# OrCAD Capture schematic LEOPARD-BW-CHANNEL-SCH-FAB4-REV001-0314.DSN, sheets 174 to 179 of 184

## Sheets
174 093_WBG - STRAPPING/MISC: size A3; title: WBG - STRAPPING/MISC
175 092_WBG - DECOUPLING 2/2: size A3; title: WBG - DECOUPLING 2/2
176 099_USB 3.0/2.0 CONNECTORS: size A3; title: USB 3/0/2/0 CONNECTORS
177 109_AST1250 CLK/VGA/USB/JTAG: size Custom; title: AST1250 CLK/VGA/USB/JTAG
178 008_POWER GOOD/RESET DIAGRAM: title: POWER GOOD/RESET DIAGRAM
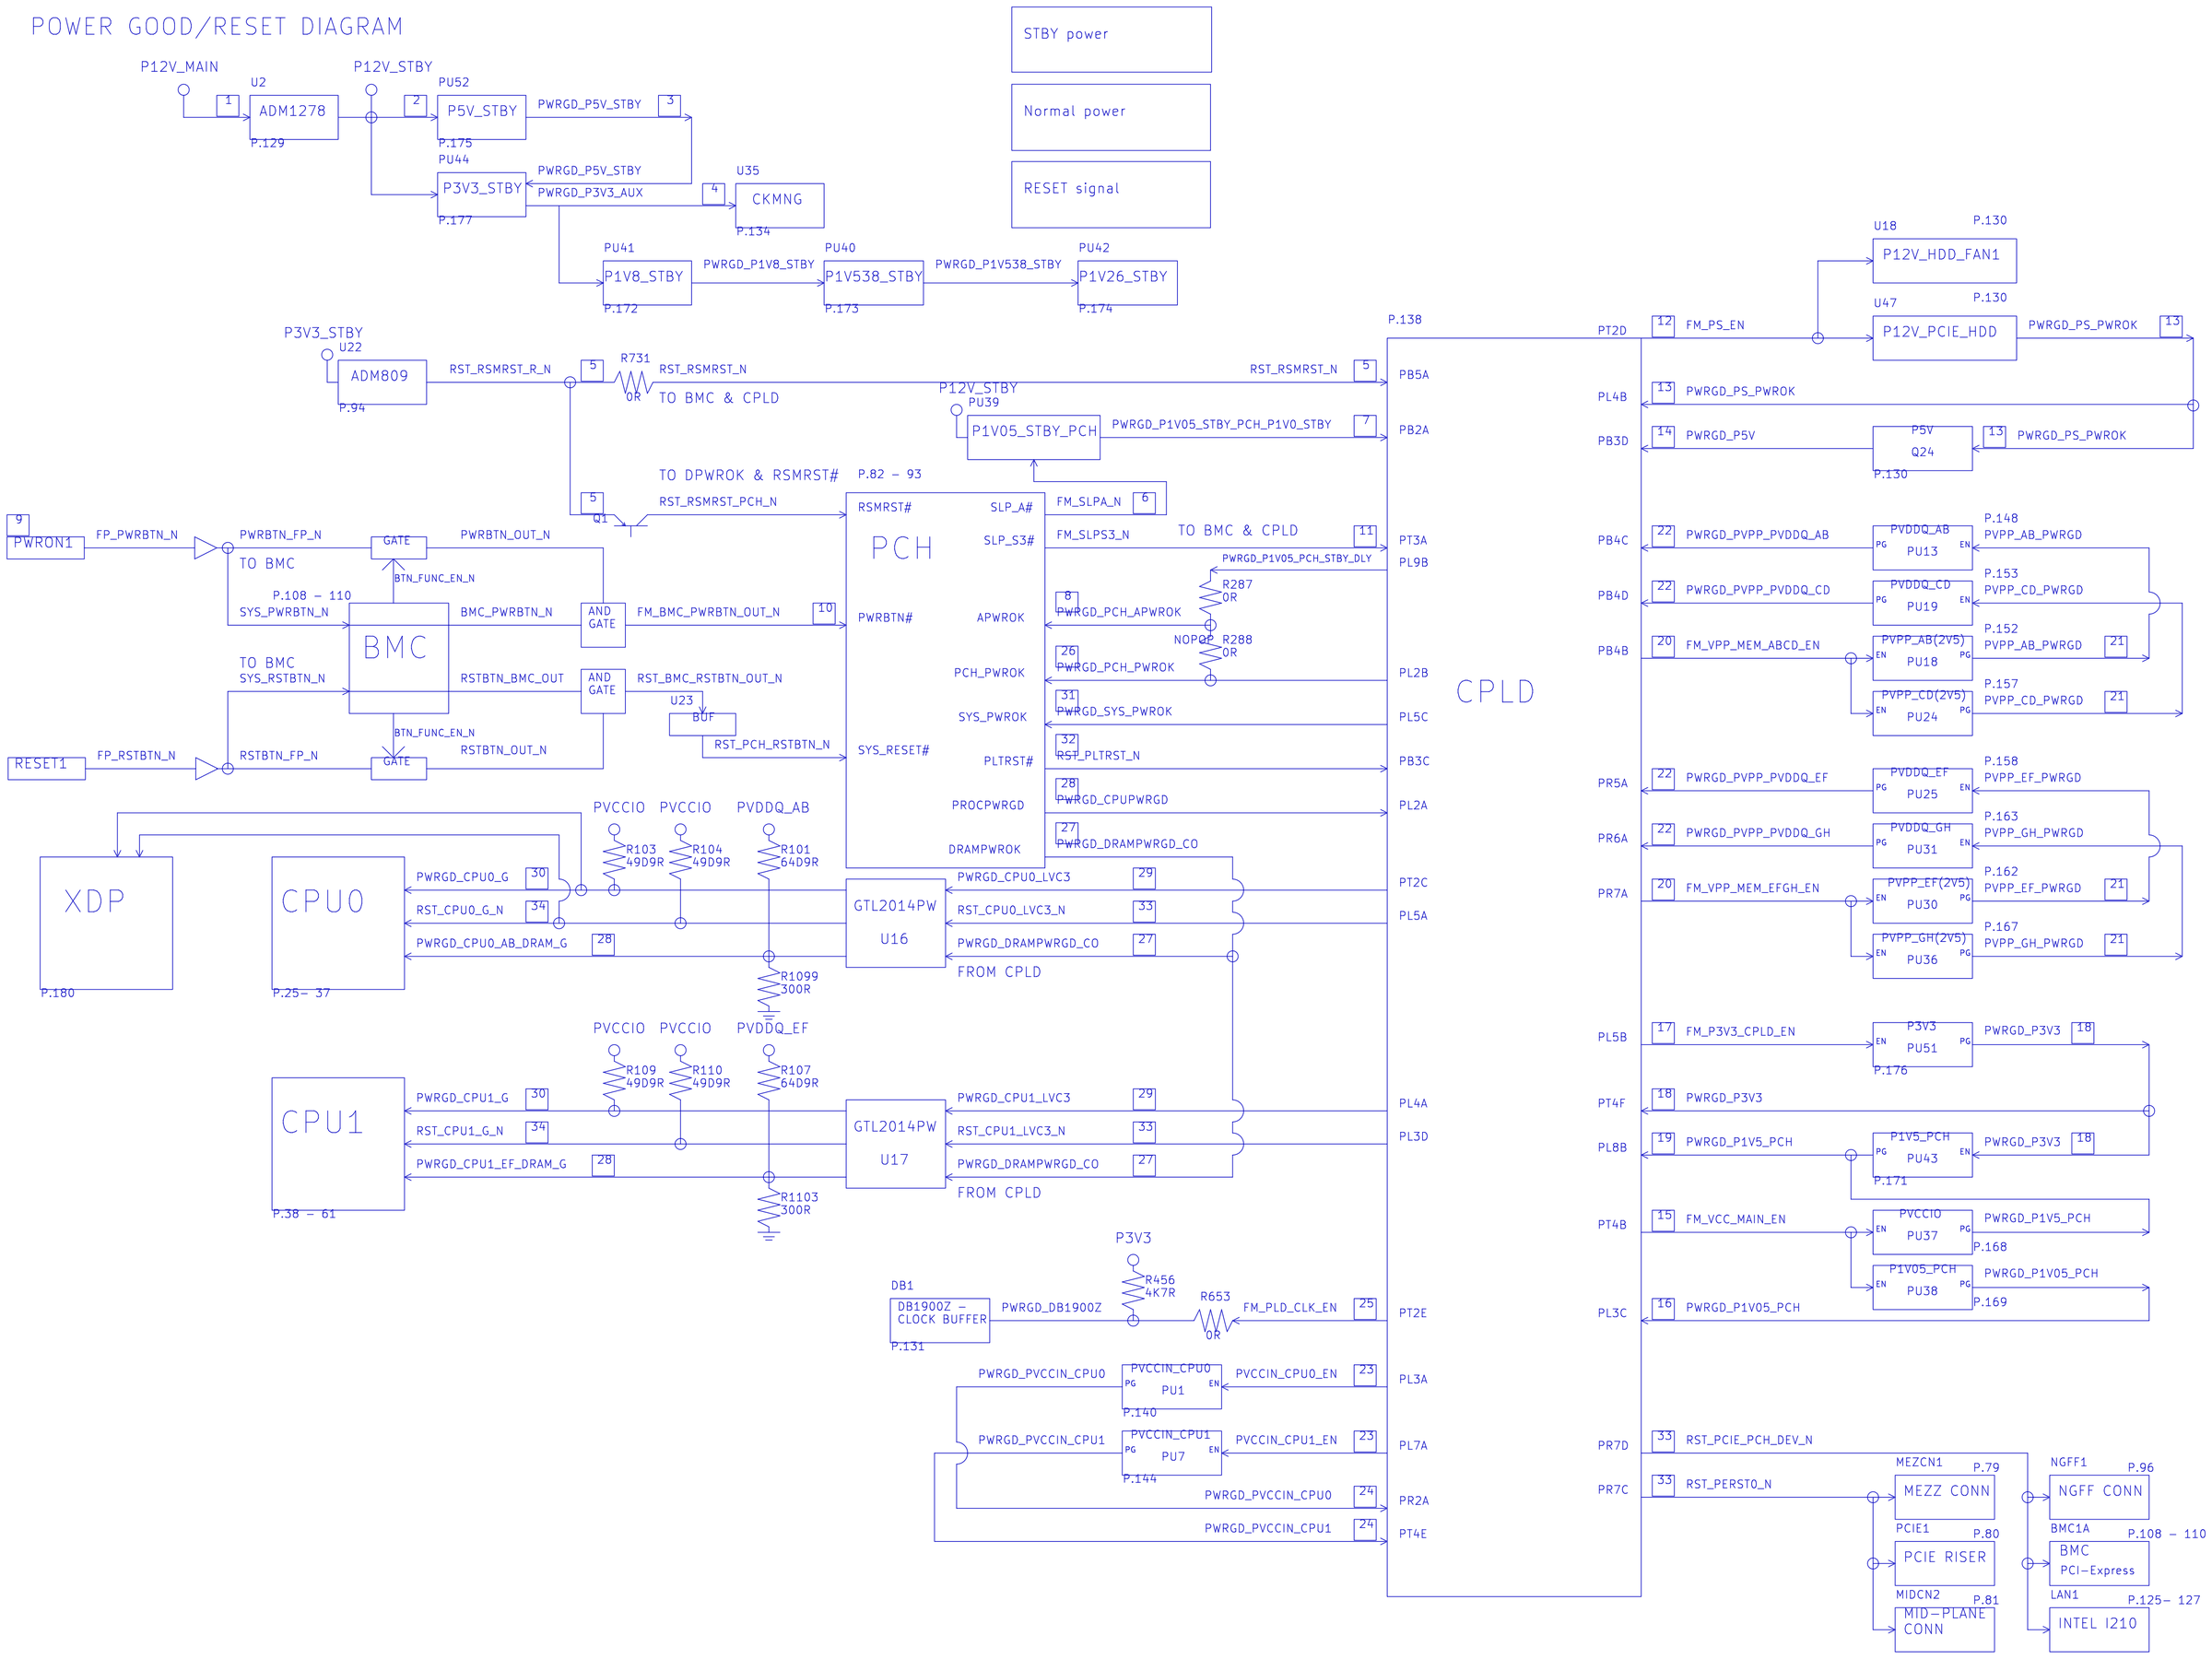
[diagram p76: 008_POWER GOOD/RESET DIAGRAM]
179 077_CPU SIDE BAND - PULL UP/DN: size A3; title: CPU SIDE BAND - PULL UP/DN
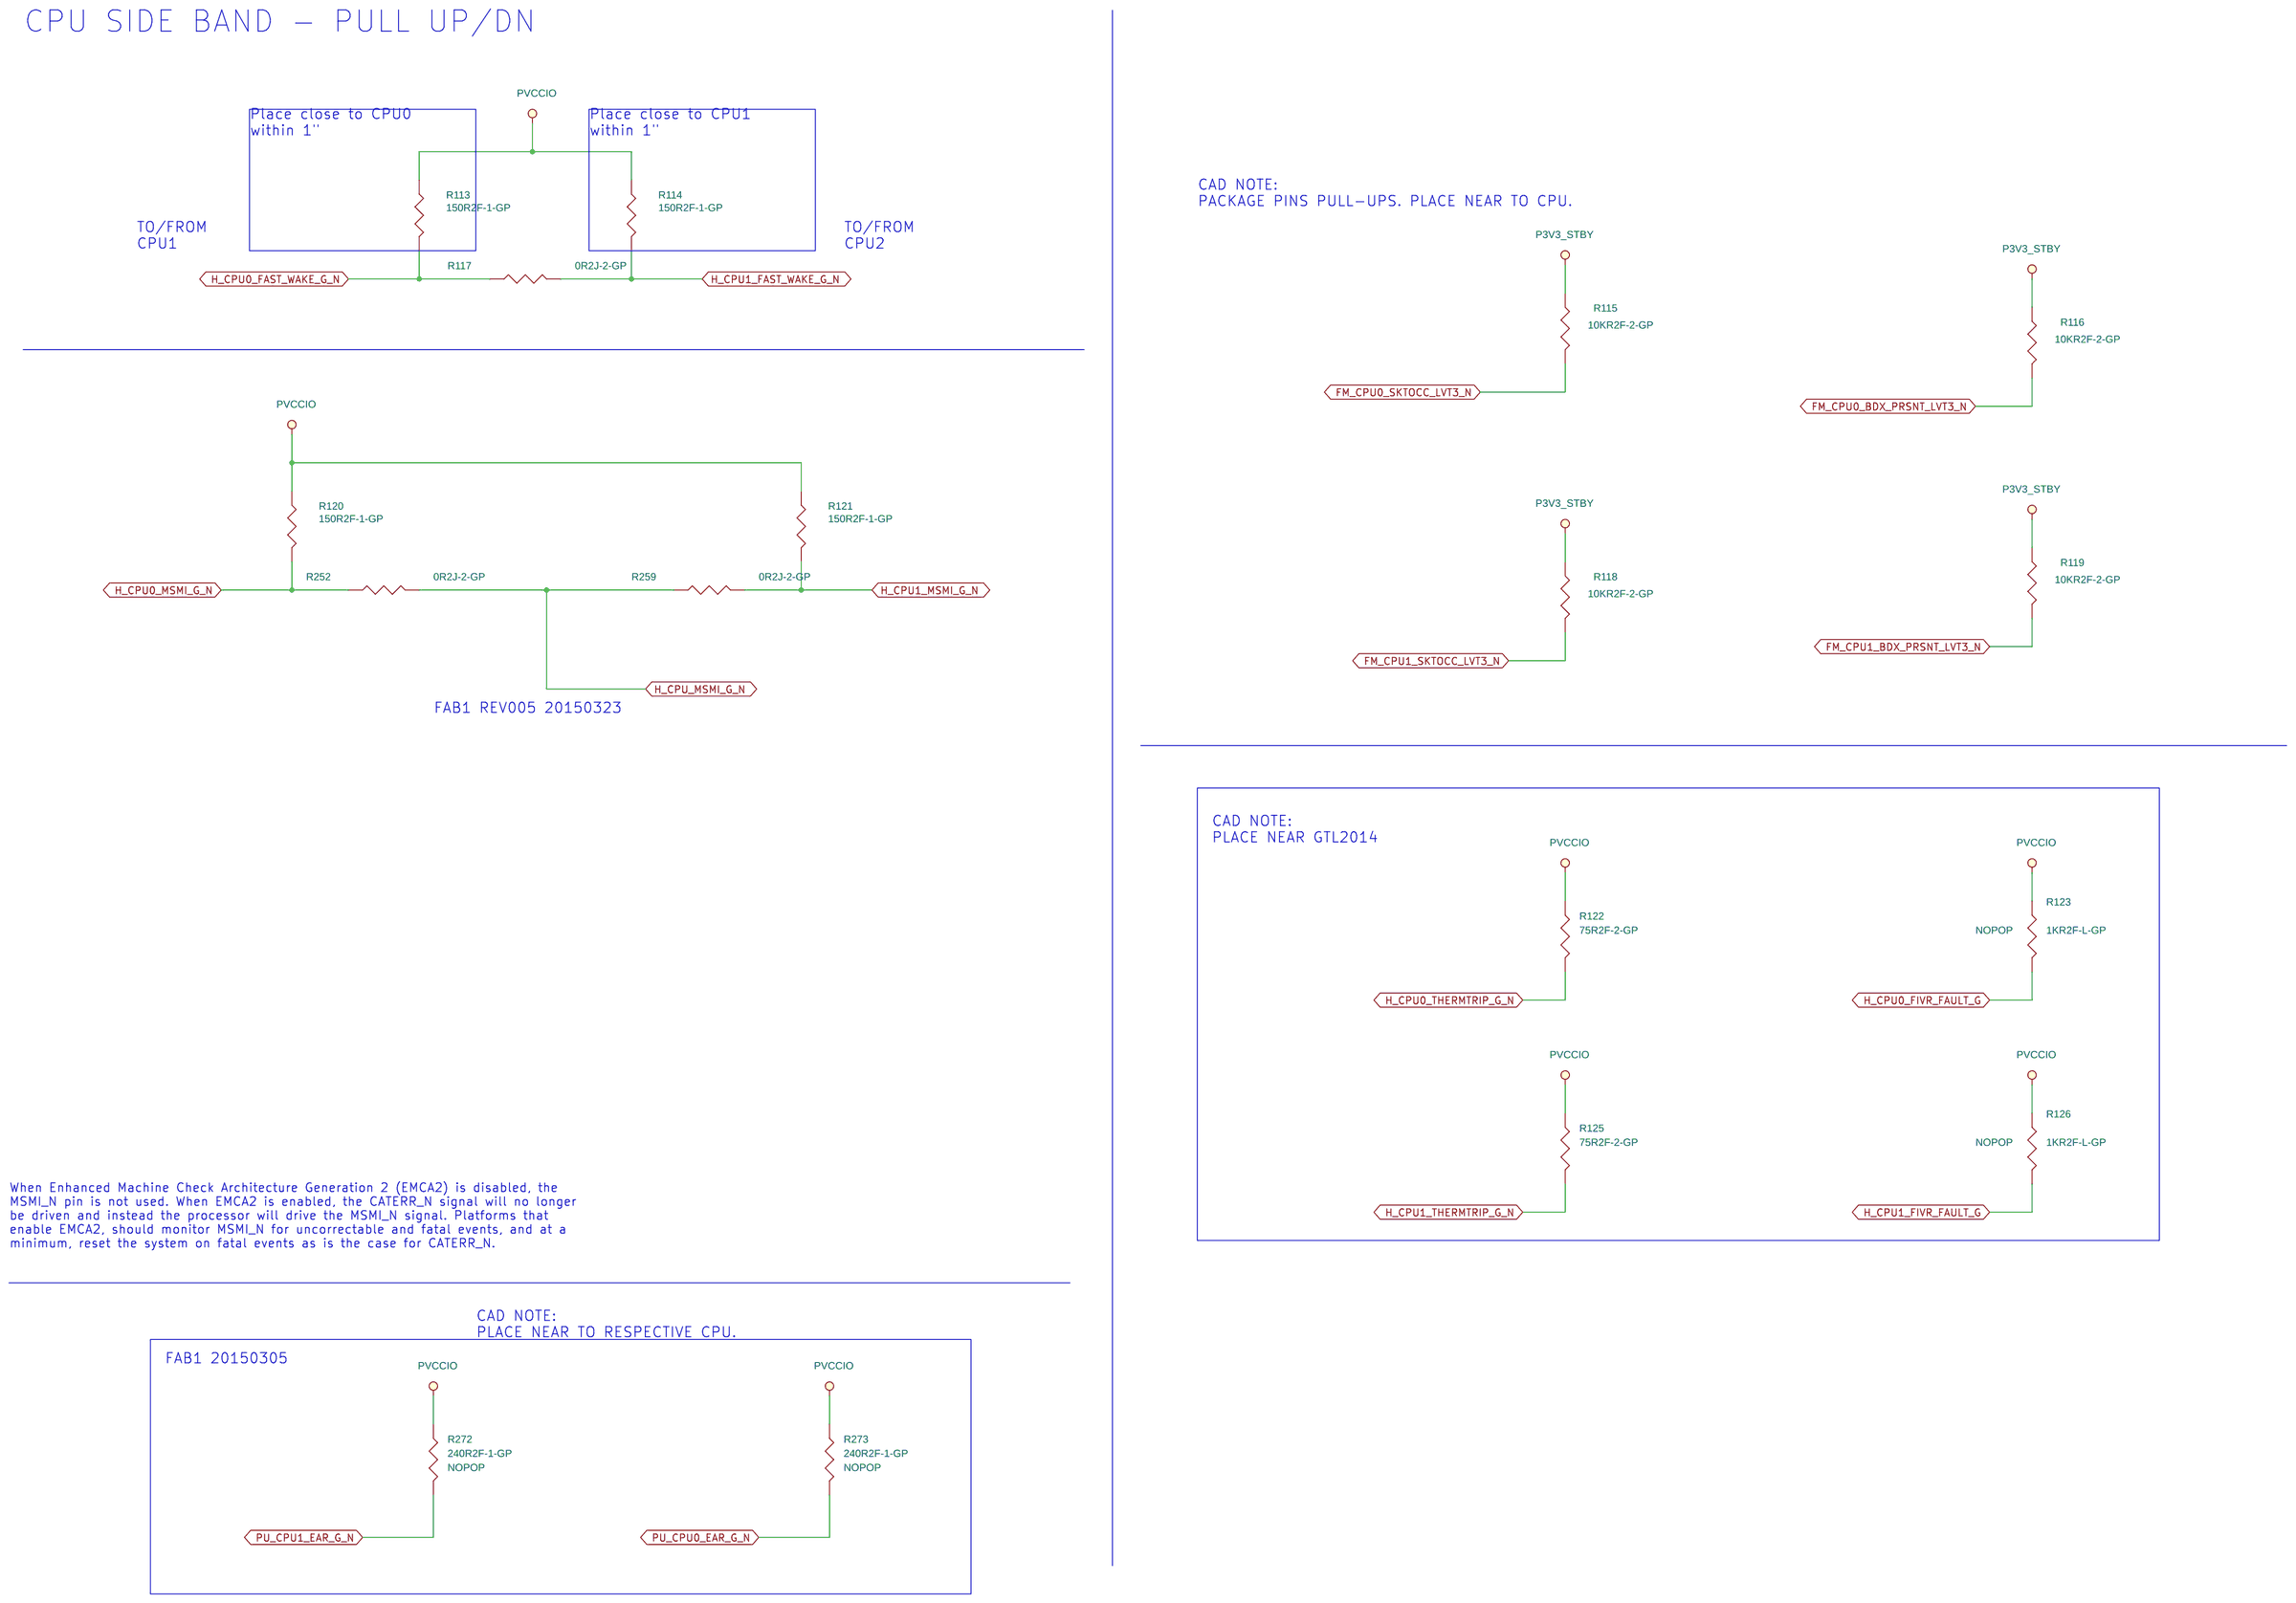
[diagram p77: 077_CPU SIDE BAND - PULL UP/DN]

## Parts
sheet 077_CPU SIDE BAND - PULL UP/DN
R113  150R2F-1-GP  [R402H16]
R114  150R2F-1-GP  [R402H16]
R115  10KR2F-2-GP  [R402H16]
R116  10KR2F-2-GP  [R402H16]
R117  0R2J-2-GP  [R402H16]
R118  10KR2F-2-GP  [R402H16]
R119  10KR2F-2-GP  [R402H16]
R120  150R2F-1-GP  [R402H16]
R121  150R2F-1-GP  [R402H16]
R122  75R2F-2-GP  [R402H16]
R123  1KR2F-L-GP  [R402H16]
R125  75R2F-2-GP  [R402H16]
R126  1KR2F-L-GP  [R402H16]
R252  0R2J-2-GP  [R402H16]
R259  0R2J-2-GP  [R402H16]
R272  240R2F-1-GP  [R402H16]
R273  240R2F-1-GP  [R402H16]
sheet 092_WBG - DECOUPLING 2/2
C257  SC1U10V2KX-4-GP  [C402H22]
C258  SC1U10V2KX-4-GP  [C402H22]
C259  SC1U10V2KX-4-GP  [C402H22]
C260  SC1U10V2KX-4-GP  [C402H22]
C261  SC1U10V2KX-4-GP  [C402H22]
C262  SC1U10V2KX-4-GP  [C402H22]
C263  SC1U10V2KX-4-GP  [C402H22]
C264  SC1U10V2KX-4-GP  [C402H22]
C265  SC10U6D3V5KX-4GP  [C805H58]
C266  SC1U10V2KX-4-GP  [C402H22]
C267  SC1U10V2KX-4-GP  [C402H22]
C268  SC1U10V2KX-4-GP  [C402H22]
C269  SC1U10V2KX-4-GP  [C402H22]
sheet 093_WBG - STRAPPING/MISC
C76  SC1U10V2KX-4-GP  [C402H22]
JP13  FCI-CON2-S-GP  [680001-202HLF]
R180  1KR2F-3-GP  [R402H16]
R191  1KR2F-3-GP  [R402H16]
R200  10KR2F-2-GP  [R402H16]
R202  10KR2F-2-GP  [R402H16]
R205  10KR2F-2-GP  [R402H16]
R207  10KR2F-2-GP  [R402H16]
R208  1KR2F-3-GP  [R402H16]
R209  1KR2F-3-GP  [R402H16]
R210  390KR2J-GP  [R402H16]
R211  1KR2F-3-GP  [R402H16]
R212  390KR2J-GP  [R402H16]
R213  10KR2F-2-GP  [R402H16]
R214  1KR2F-3-GP  [R402H16]
R215  1KR2F-3-GP  [R402H16]
R218  3K3R2F-2-GP  [R402H16]
R238  100R2F-L1-GP-U  [R402H14]
R330  0R2J-2-GP  [R402H16]
R862  100R2F-L1-GP-U  [R402H14]
R872  1KR2F-3-GP  [R402H16]
R873  1KR2F-3-GP  [R402H16]
R916  10KR2F-2-GP  [R402H16]
U82  NC7SB3157P6X-2GP  [UMT6H44]
sheet 099_USB 3.0/2.0 CONNECTORS
C332  SCD1U10V2KX-5GP  [C402H22]
C333  SCD1U10V2KX-5GP  [C402H22]
C334  SCD1U10V2KX-5GP  [C402H22]
C335  SCD1U10V2KX-5GP  [C402H22]
C7318  SCD1U16V2KX-3GP  [C402H22]
C7319  SC1KP50V2KX-1GP  [C402H22]
C7320  SC1KP50V2KX-1GP  [C402H22]
D2  PESD5V0X1BQ-1-GP  [SC75-1D6-312H24]
D5  PESD5V0X1BQ-1-GP  [SC75-1D6-312H24]
L7  FILTER-4P-204-GP  [FILTER2012-4PH48]
L28  DLW21HN900SQ2LGP-U  [L2012-4P-1MH40]
L31  DLW21HN900SQ2LGP-U  [L2012-4P-1MH40]
L35  DLW21HN900SQ2LGP-U  [L2012-4P-1MH40]
L38  DLW21HN900SQ2LGP-U  [L2012-4P-1MH40]
L47  DLW21HN900SQ2LGP-U  [L2012-4P-1MH40]
R326  0R3J-0-U-GP  [R603H22]
R331  0R3J-0-U-GP  [R603H22]
R399  10KR2F-2-GP  [R402H16]
R400  10KR2F-2-GP  [R402H16]
R577  0R3J-0-U-GP  [R603H22]
R578  0R3J-0-U-GP  [R603H22]
R594  0R3J-0-U-GP  [R603H22]
R595  0R3J-0-U-GP  [R603H22]
R598  0R3J-0-U-GP  [R603H22]
R599  0R3J-0-U-GP  [R603H22]
R784  0R3J-0-U-GP  [R603H22]
R851  0R3J-0-U-GP  [R603H22]
R6609  10KR2F-2-GP  [R402H16]
R6610  10KR2F-2-GP  [R402H16]
TC1  ST220U10VDM-9GP  [CT7343H123]
TC2  ST220U10VDM-9GP  [CT7343H123]
U30  DF10G7M1N-GP  [DFN10G2510-1H22]
U32  DF10G7M1N-GP  [DFN10G2510-1H22]
U169  AP2192MPG-13-GP  [MSOP8-1G195165H44]
USB1  SKT-USB13-27-GP  [SKT-USB13-148074]
USB2  SKT-USB13-119-GP  [SKT-USB13-071258]
sheet 107_AST1250 PCIE_LPC_DDR3_I2C
BMC1  AST1250A1-GP  [BGA408D19H52]  (sections A,B,C,D)
sheet 109_AST1250 CLK/VGA/USB/JTAG
C153  SC1U10V2KX-4-GP  [C402H22]
C154  SCD1U16V2KX-3GP  [C402H22]
C495  SC4D7U16V5KX-1-GP  [C805H56]
C512  SC100P50V2JN-3GP  [C402H22]
C7284  SC1U10V2KX-4-GP  [C402H22]
L23  BLM21PG331SN1D-2-GP  [L805H42]
OSC2  OSC-48MHZ-28-GP  [OSC-3225-4P-3H48]
Q21  2N7002-7F-GP  [SOT23DGS2D4H44]
R268  10KR2F-2-GP  [R402H16]
R333  10KR2F-2-GP  [R402H16]
R348  10KR2F-2-GP  [R402H16]
R354  10KR2F-2-GP  [R402H16]
R357  10KR2F-2-GP  [R402H16]
R358  10KR2F-2-GP  [R402H16]
R359  10KR2F-2-GP  [R402H16]
R367  10KR2F-2-GP  [R402H16]
R511  10KR2F-2-GP  [R402H16]
R515  10KR2F-2-GP  [R402H16]
R751  0R2J-2-GP  [R402H16]
R752  0R2J-2-GP  [R402H16]
R756  0R2J-2-GP  [R402H16]
R757  0R2J-2-GP  [R402H16]
R771  0R2J-2-GP  [R402H16]
R787  0R2J-2-GP  [R402H16]
R909  8K2R2J-3-GP  [R402H16]
R910  10KR2F-2-GP  [R402H16]
R911  47KR2F-GP  [R402H16]
R913  10KR2F-2-GP  [R402H16]
R914  4K7R2F-GP  [R402H16]
R915  47KR2F-GP  [R402H16]
R917  100R2F-L1-GP-U  [R402H14]
R923  10R2F-L-GP  [R402H14]
R924  0R2J-2-GP  [R402H16]
R925  100R2F-L1-GP-U  [R402H14]
R926  0R2J-2-GP  [R402H16]
R927  47KR2F-GP  [R402H16]
R929  0R2J-2-GP  [R402H16]
R930  47KR2F-GP  [R402H16]
R931  47KR2F-GP  [R402H16]
R934  47KR2F-GP  [R402H16]
R936  4K7R2F-GP  [R402H16]
R1036  10KR2F-2-GP  [R402H16]
R2033  10KR2F-2-GP  [R402H16]
R2073  0R2J-2-GP  [R402H16]
U166  SN74LVC1G07DCKR-GP  [SC70-5H44]

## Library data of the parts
R113 R114 R120 R121 = 150R2F-1-GP: CHIP RES 150 F 1/16W 0402; GREENDFACTOR: R2_SA;HF_SA;G_SA;; Package Type: SMD-RG; Part Number: 64.15005.6DL; SPEC: http://wpqssvr.wistron.com.tw:7001/wpqs/servlet/COM.qpart.Attachment?PartNumber=64.15005.6DL
R115 R116 R118 R119 = 10KR2F-2-GP: CHIP RES 10K F 1/16W 0402; GREENDFACTOR: R2_SA;HF_SA;G_SA;; Part Number: 64.10025.6DL; Part Type: SMD-RG; SPEC: http://wpqssvr.wistron.com.tw:7001/wpqs/servlet/COM.qpart.Attachment?PartNumber=64.10025.6DL
R117 R252 R259 R330 = 0R2J-2-GP: CHIP RES 0 J 1/16W 0402; Category: PCH; DESCRIPTIO: CHIP RES 0 J 1/16W 0402; GREENDFACTOR: R2_SA;HF_SA;G_SA;; Package Type: SMD-RG; Part Number: 63.R0034.1DL; Part Type: SMD-RG; SPEC: http://wpqssvr.wistron.com.tw:7001/wpqs/servlet/COM.qpart.Attachment?PartNumber=63.R0034.1DL; VENDORPARTNUMBER: RM04JTN0/RTT02000JTH/RR0510X-000-XN/RC0402JR-070RL/WR04X000 PTL
R122 R125 = 75R2F-2-GP: CHIP RES 75 F 1/16W 0402; Category: XDP; DESCRIPTIO: CHIP RES 75 F 1/16W 0402; GREENDFACTOR: R2_SA;HF_SA;G_SA;; Package Type: SMD-RG; Part Number: 64.75R05.6DL; Part Type: SMD-RG; SPEC: http://wpqssvr.wistron.com.tw:7001/wpqs/servlet/COM.qpart.Attachment?PartNumber=64.75R05.6DL; VENDORPARTNUMBER: RM04FTN75R0 / RTT0275R0FTH / RR0510S-750-FN / RC0402FR-0775RL/WR04X75R0FTL
R123 R126 = 1KR2F-L-GP: CHIP RES 1K F 1/16W 0402; Category: CPU SIDE BAND; POP?: NOPOP; Part Number: 64.10015.L1L; Part Type: SMD-RG2
R272 R273 = 240R2F-1-GP: CHIP RES 240 F 1/16W 0402(ROHS; Category: CPU SIDE BAND; POP?: NOPOP; Part Number: 64.24005.6DL; Part Type: SMD-RG
C76 C257-C261 C263 C264 C266-C269 = SC1U10V2KX-4-GP: CHIP CAP C 1U 10V K 0402 X6S; GREENDFACTOR: R2_SA;HF_SA;; Part Number: 78.10523.8FL; Part Type: SMD-BCG6; SPEC: http://wpqssvr.wistron.com.tw:7001/wpqs/servlet/COM.qpart.Attachment?PartNumber=78.10523.8FL
C153 C262 C7284 = SC1U10V2KX-4-GP: CHIP CAP C 1U 10V K 0402 X6S; GREENDFACTOR: R2_SA;HF_SA;; POP?: NOPOP; Part Number: 78.10523.8FL; Part Type: SMD-BCG6; SPEC: http://wpqssvr.wistron.com.tw:7001/wpqs/servlet/COM.qpart.Attachment?PartNumber=78.10523.8FL
C265 = SC10U6D3V5KX-4GP: CHIP CAP C 10U 6.3V K0805 X7R; GREENDFACTOR: R2_SA;HF_SA;G_SA;; Part Number: 78.10620.21L; Part Type: SMD-BCG; SPEC: http://wpqssvr.wistron.com.tw:7001/wpqs/servlet/COM.qpart.Attachment?PartNumber=78.10620.21L
JP13 = FCI-CON2-S-GP: HEAD ML 1R2P 68001-202HLF; Category: PCH; GREENDFACTOR: R_SA;; Package Type: CONN-G4; Part Number: 21.65007.102; Part Type: CONN-G4; SPEC: http://wpqssvr.wistron.com.tw:7001/wpqs/servlet/COM.qpart.Attachment?PartNumber=21.65007.102
R180 R191 R208 R209 R211 R214 R872 R873 = 1KR2F-3-GP: CHIP RES 1K F 1/16W 0402; Category: PCH; GREENDFACTOR: R2_SA;HF_SA;G_SA;; POP?: NOPOP; Package Type: SMD-RG; Part Number: 64.10015.6DL; Part Type: SMD-RG; SPEC: http://wpqssvr.wistron.com.tw:7001/wpqs/servlet/COM.qpart.Attachment?PartNumber=64.10015.6DL; VENDORPARTNUMBER: RM04FTN1001 / RTT021001FTH / RR0510S-1001-FN / RC0402FR-071KL/WR04X1001FTL
R200 R202 R205 R207 R213 R916 = 10KR2F-2-GP: CHIP RES 10K F 1/16W 0402; Category: PCH; DESCRIPTIO: CHIP RES 10K F 1/16W 0402; GREENDFACTOR: R2_SA;HF_SA;G_SA;; Package Type: SMD-RG; Part Number: 64.10025.6DL; Part Type: SMD-RG; SPEC: http://wpqssvr.wistron.com.tw:7001/wpqs/servlet/COM.qpart.Attachment?PartNumber=64.10025.6DL; VENDORPARTNUMBER: RM04FTN1002 / RTT021002FTH / RR0510S-103-FN / RC0402FR-0710KL/WR04X1002FTL
R210 R212 = 390KR2J-GP: CHIP RES 390K 1/16W J 0402; GREENDFACTOR: R2_SA;HF_SA;G_SA;; Package Type: RCL_GP; Part Number: 63.39434.1DL; SPEC: http://wpqssvr.wistron.com.tw:7001/wpqs/servlet/COM.qpart.Attachment?PartNumber=63.39434.1DL
R215 = 1KR2F-3-GP: CHIP RES 1K F 1/16W 0402; Category: PCH; GREENDFACTOR: R2_SA;HF_SA;G_SA;; Package Type: SMD-RG; Part Number: 64.10015.6DL; Part Type: SMD-RG; SPEC: http://wpqssvr.wistron.com.tw:7001/wpqs/servlet/COM.qpart.Attachment?PartNumber=64.10015.6DL; VENDORPARTNUMBER: RM04FTN1001 / RTT021001FTH / RR0510S-1001-FN / RC0402FR-071KL/WR04X1001FTL
R218 = 3K3R2F-2-GP: CHIP RES 3.3K F 1/16W 0402; Category: BMC; DESCRIPTIO: CHIP RES 3.3K F 1/16W 0402; GREENDFACTOR: R2_SA;HF_SA;G_SA;; Package Type: SMD-RG; Part Number: 64.33015.6DL; Part Type: SMD-RG; SPEC: http://wpqssvr.wistron.com.tw:7001/wpqs/servlet/COM.qpart.Attachment?PartNumber=64.33015.6DL; VENDORPARTNUMBER: RM04FTN3301/RTT023301FTH/RR0510S-332-FN/RC0402FR-073K3L
R238 = 100R2F-L1-GP-U: CHIP RES 100 F 1/16W 0402; Category: PCH; Part Number: 64.10005.6DL; Part Type: SMD-RG
R862 = 100R2F-L1-GP-U: CHIP RES 100 F 1/16W 0402; Category: PCH; POP?: NOPOP; Part Number: 64.10005.6DL; Part Type: SMD-RG
U82 = NC7SB3157P6X-2GP: IC SW NC7SB3157P6X SC70(L/F); Alternate: 73.03157.B0H; Category: PCH; Change to: 73.03157.A0J; DESCRIPTIO: IC SW NC7SB3157P6X SC70(L/F); GREENDFACTOR: R2_SA;; Note: The same as CRB; Package Type: DISCRET-G; Part Number: 73.03157.D0H; Part Type: DISCRET-G; SPEC: http://wpqssvr.wistron.com.tw:7001/wpqs/servlet/COM.qpart.Attachment?PartNumber=73.03157.D0H; VENDORPARTNUMBER: NC7SB3157P6X
C332-C335 = SCD1U10V2KX-5GP: CHIP CAP C 0.1U 10V K0402 X7R; Belong: POP; CATEGORIES: CAP_1.xV; Category: TMP421; GREENDFACTOR: R2_SA;R_SA;HF_SA;G_SA;; MAIN_SOURCE: M; Part Number: 78.10423.2FL; Part Type: SMD-BCG; SPEC: http://wpqssvr.wistron.com.tw:7001/wpqs/servlet/COM.qpart.Attachment?PartNumber=78.10423.2FL
C7318 = SCD1U16V2KX-3GP: CHIP CAP C 0.1U 16V K0402 X7R; CATEGORIES: CAP_1.xV; GREENDFACTOR: R2_SA;HF_SA;G_SA;; MAIN_SOURCE: M; Part Number: 78.10421.2FL; Part Type: SMD-BCG; SPEC: http://wpqssvr.wistron.com.tw:7001/wpqs/servlet/COM.qpart.Attachment?PartNumber=78.10421.2FL
C7319 C7320 = SC1KP50V2KX-1GP: CHIP CAP 1000P50V K0402 X7R(RO; CATEGORIES: CAP_Small; GREENDFACTOR: R2_SA;HF_SA;G_SA;; MAIN_SOURCE: M; Package Type: SMD-BCG; Part Number: 78.10224.2FL; SPEC: http://wpqssvr.wistron.com.tw:7001/wpqs/servlet/COM.qpart.Attachment?PartNumber=78.10224.2FL
D2 D5 = PESD5V0X1BQ-1-GP: IC DIODE ESD PESD5V0X1BQ SOT663; GREENDFACTOR: R2_SA;HF_SA;; Package Type: DISCRET-G7; Part Number: 75.005V0.07D; SPEC: http://wpqssvr.wistron.com.tw:7001/wpqs/servlet/COM.qpart.Attachment?PartNumber=75.005V0.07D
L7 = FILTER-4P-204-GP: CHIP COMM MODE FILTER MCF21T-900M-N2; GREENDFACTOR: R2_C;HF_C;; Part Number: 068.MCF21.2001; Part Type: DISCRET-GB2; SPEC: http://wpqssvr.wistron.com.tw:7001/wpqs/servlet/COM.qpart.Attachment?PartNumber=068.MCF21.2001
L28 L31 L35 L47 = DLW21HN900SQ2LGP-U: CHIP CHOKE DLW21HN900SQ2L; Category: USB; GREENDFACTOR: R2_SA;HF_SA;G_SA;; POP?: NOPOP; Package Type: DISCRET-G; Part Number: 68.00201.141; Part Type: DISCRET-G; SPEC: http://wpqssvr.wistron.com.tw:7001/wpqs/servlet/COM.qpart.Attachment?PartNumber=68.00201.141; change to: 77P0745AA
L38 = DLW21HN900SQ2LGP-U: CHIP CHOKE DLW21HN900SQ2L; Alternate: 69.10084.071; Category: USB; DESCRIPTIO: CHIP CHOKE DLW21HN900SQ2L; GREENDFACTOR: R2_SA;HF_SA;G_SA;; Package Type: DISCRET-G; Part Number: 68.00201.141; Part Type: DISCRET-G; SPEC: http://wpqssvr.wistron.com.tw:7001/wpqs/servlet/COM.qpart.Attachment?PartNumber=68.00201.141; VENDORPARTNUMBER: DLW21HN900SQ2L
R326 R331 R577 R578 R594 R595 R598 R599 R784 R851 = 0R3J-0-U-GP: CHIP RES 0 J 1/10W 0603; Category: USB; DESCRIPTIO: CHIP RES 0 J 1/10W 0603; GREENDFACTOR: R2_SA;HF_SA;G_SA;; Package Type: RCL_GP; Part Number: 63.00000.00L; Part Type: RCL_GP; SPEC: http://wpqssvr.wistron.com.tw:7001/wpqs/servlet/COM.qpart.Attachment?PartNumber=63.00000.00L; VENDORPARTNUMBER: RM06JTN0 / RTT03000JTP / RC0603JR-070RL / WR06X000 PTL
R333 R399 R400 R2033 = 10KR2F-2-GP: CHIP RES 10K F 1/16W 0402; GREENDFACTOR: R2_SA;HF_SA;G_SA;; POP?: NOPOP; Package Type: SMD-RG; Part Number: 64.10025.6DL; SPEC: http://wpqssvr.wistron.com.tw:7001/wpqs/servlet/COM.qpart.Attachment?PartNumber=64.10025.6DL
R354 R357-R359 R367 R6609 R6610 = 10KR2F-2-GP: CHIP RES 10K F 1/16W 0402; GREENDFACTOR: R2_SA;HF_SA;G_SA;; Package Type: SMD-RG; Part Number: 64.10025.6DL; SPEC: http://wpqssvr.wistron.com.tw:7001/wpqs/servlet/COM.qpart.Attachment?PartNumber=64.10025.6DL
TC1 TC2 = ST220U10VDM-9GP: CHIP CAP T220U 10V M7343 L(GP); GREENDFACTOR: R2_SA;G_SA;; Part Number: 80.22711.L02; Part Type: SMD-TCG; SPEC: http://wpqssvr.wistron.com.tw:7001/wpqs/servlet/COM.qpart.Attachment?PartNumber=80.22711.L02
U30 U32 = DF10G7M1N-GP: IC DIODE ESD DF10G7M1N DFN 10P; GREENDFACTOR: R2_SA;HF_SA;; Part Number: 75.00107.073; Part Type: DISCRET-G7; SPEC: http://wpqssvr.wistron.com.tw:7001/wpqs/servlet/COM.qpart.Attachment?PartNumber=75.00107.073
U169 = AP2192MPG-13-GP: IC PWR SW AP2192MPG-13 MSOP 8P; GREENDFACTOR: R2_SA;; Part Number: 74.02192.079; Part Type: DISCRET-G7; SPEC: http://wpqssvr.wistron.com.tw:7001/wpqs/servlet/COM.qpart.Attachment?PartNumber=74.02192.079
USB1 = SKT-USB13-27-GP: SKT USB 3.0 ABA-USB-126-K01 VERTICAL; GREENDFACTOR: R2_SA;; Part Number: 22.10341.291; Part Type: SOCKET-G4; SPEC: http://wpqssvr.wistron.com.tw:7001/wpqs/servlet/COM.qpart.Attachment?PartNumber=22.10341.291
USB2 = SKT-USB13-119-GP: SKT USB 3.0 UEA3119C-4FB1-4H; GREENDFACTOR: R2_C;HF_C;; Part Number: 22.10341.G31; Part Type: SOCKET-G6; SPEC: http://wpqssvr.wistron.com.tw:7001/wpqs/servlet/COM.qpart.Attachment?PartNumber=22.10341.G31
BMC1 = AST1250A1-GP: IC BMC AST1250A1-GP TFBGA 408P; GREENDFACTOR: R2_C;; Part Number: 71.01250.A0U; Part Type: ASIC2-G7; SPEC: http://wpqssvr.wistron.com.tw:7001/wpqs/servlet/COM.qpart.Attachment?PartNumber=71.01250.A0U
C154 = SCD1U16V2KX-3GP: CHIP CAP C 0.1U 16V K0402 X7R; CATEGORIES: CAP_1.xV; Category: BMC; GREENDFACTOR: R2_SA;HF_SA;G_SA;; Level: SMD; MAIN_SOURCE: M; Part Number: 78.10421.2FL; Part Type: SMD-BCG; SPEC: http://wpqssvr.wistron.com.tw:7001/wpqs/servlet/COM.qpart.Attachment?PartNumber=78.10421.2FL; Status: POP
C495 = SC4D7U16V5KX-1-GP: CHIP CAP C 4.7U 16V K0805 X7R; GREENDFACTOR: R2_SA;HF_SA;G_SA;; Part Number: 78.47521.21L; Part Type: SMD-BCG2; SPEC: http://wpqssvr.wistron.com.tw:7001/wpqs/servlet/COM.qpart.Attachment?PartNumber=78.47521.21L
C512 = SC100P50V2JN-3GP: CHIP CAP 100P50V J0402 NPO(ROH; CATEGORIES: CAP_Small; Category: BMC; DESCRIPTIO: CHIP CAP 100P50V J0402 NPO(ROH; GREENDFACTOR: R2_SA;HF_SA;G_SA;; MAIN_SOURCE: M; Package Type: SMD-BCG; Part Number: 78.10134.1FL; Part Type: SMD-BCG; SPEC: http://wpqssvr.wistron.com.tw:7001/wpqs/servlet/COM.qpart.Attachment?PartNumber=78.10134.1FL; VENDORPARTNUMBER: CM05CG101J50AH/C1005NP0101JGT/GRM1555C1H101JZ01D/223886915101/CL05C101JB5NNNC/UMK105CH101JV-F/C1005C0G1H101JT/0402N101J500LT
L23 = BLM21PG331SN1D-2-GP: CHIP BEAD BLM21PG331SN1D MURAT; GREENDFACTOR: R2_SA;G_SA;; Part Number: 68.00084.571; Part Type: DISCRET-G7; SPEC: http://wpqssvr.wistron.com.tw:7001/wpqs/servlet/COM.qpart.Attachment?PartNumber=68.00084.571
OSC2 = OSC-48MHZ-28-GP: OSC 48MHZ 50PPM 15PF 3.3V HSO321S SMD; GREENDFACTOR: R2_SA;; Part Number: 82.20013.291; Part Type: DISCRET-G8; SPEC: http://wpqssvr.wistron.com.tw:7001/wpqs/servlet/COM.qpart.Attachment?PartNumber=82.20013.291
Q21 = 2N7002-7F-GP: FET MOS 2N7002-7-F NC SOT-23; GREENDFACTOR: R2_SA;HF_SA;G_SA;; Part Number: 84.27002.N31; Part Type: DISCRET-G; SPEC: http://wpqssvr.wistron.com.tw:7001/wpqs/servlet/COM.qpart.Attachment?PartNumber=84.27002.N31
R268 R348 R511 R515 = 10KR2F-2-GP: CHIP RES 10K F 1/16W 0402; Category: BMC; DESCRIPTIO: CHIP RES 10K F 1/16W 0402; GREENDFACTOR: R2_SA;HF_SA;G_SA;; Package Type: SMD-RG; Part Number: 64.10025.6DL; Part Type: SMD-RG; SPEC: http://wpqssvr.wistron.com.tw:7001/wpqs/servlet/COM.qpart.Attachment?PartNumber=64.10025.6DL; VENDORPARTNUMBER: RM04FTN1002 / RTT021002FTH / RR0510S-103-FN / RC0402FR-0710KL/WR04X1002FTL
R751 R752 R756 R757 R771 R787 R2073 = 0R2J-2-GP: CHIP RES 0 J 1/16W 0402; GREENDFACTOR: R2_SA;HF_SA;G_SA;; Package Type: SMD-RG; Part Number: 63.R0034.1DL; SPEC: http://wpqssvr.wistron.com.tw:7001/wpqs/servlet/COM.qpart.Attachment?PartNumber=63.R0034.1DL
R909 = 8K2R2J-3-GP: CHIP RES 8.2K J 1/16W 0402; GREENDFACTOR: R2_SA;HF_SA;G_SA;; Part Number: 63.82234.1DL; Part Type: SMD-RG; SPEC: http://wpqssvr.wistron.com.tw:7001/wpqs/servlet/COM.qpart.Attachment?PartNumber=63.82234.1DL
R910 = 10KR2F-2-GP: CHIP RES 10K F 1/16W 0402; Category: BMC; GREENDFACTOR: R2_SA;R_SA;HF_SA;G_SA;; Level: SMD; POP?: NOPOP; Part Number: 64.10025.6DL; Part Type: SMD-RG; SPEC: http://wpqssvr.wistron.com.tw:7001/wpqs/servlet/COM.qpart.Attachment?PartNumber=64.10025.6DL; Status: POP
R911 R915 R927 R930 R934 = 47KR2F-GP: CHIP RES 47K F 1/16W 0402; Category: BMC; GREENDFACTOR: R2_SA;R_SA;HF_SA;G_SA;; Level: SMD; Part Number: 64.47025.6DL; Part Type: RCL_GP; SPEC: http://wpqssvr.wistron.com.tw:7001/wpqs/servlet/COM.qpart.Attachment?PartNumber=64.47025.6DL; Status: POP
R913 = 10KR2F-2-GP: CHIP RES 10K F 1/16W 0402; Category: BMC; GREENDFACTOR: R2_SA;R_SA;HF_SA;G_SA;; Level: SMD; Part Number: 64.10025.6DL; Part Type: SMD-RG; SPEC: http://wpqssvr.wistron.com.tw:7001/wpqs/servlet/COM.qpart.Attachment?PartNumber=64.10025.6DL; Status: POP
R914 = 4K7R2F-GP: CHIP RES 4.7K F 1/16W 0402; Category: BMC; GREENDFACTOR: R2_SA;HF_SA;G_SA;; Level: SMD; POP?: NOPOP; Part Number: 64.47015.6DL; Part Type: RCL_GP; SPEC: http://wpqssvr.wistron.com.tw:7001/wpqs/servlet/COM.qpart.Attachment?PartNumber=64.47015.6DL; Status: POP
R917 = 100R2F-L1-GP-U: CHIP RES 100 F 1/16W 0402; Category: BMC; GREENDFACTOR: R2_SA;R_SA;HF_SA;G_SA;; Level: SMD; Part Number: 64.10005.6DL; Part Type: SMD-RG; SPEC: http://wpqssvr.wistron.com.tw:7001/wpqs/servlet/COM.qpart.Attachment?PartNumber=64.10005.6DL; Status: POP
R923 = 10R2F-L-GP: CHIP RES 10 F 1/16W 0402; Category: BMC; GREENDFACTOR: R2_SA;R_SA;HF_SA;G_SA;; Level: SMD; Part Number: 64.10R05.6DL; Part Type: SMD-RG; SPEC: http://wpqssvr.wistron.com.tw:7001/wpqs/servlet/COM.qpart.Attachment?PartNumber=64.10R05.6DL; Status: POP
R924 R929 = 0R2J-2-GP: CHIP RES 0 J 1/16W 0402; Category: BMC; GREENDFACTOR: R2_SA;R_SA;HF_SA;G_SA;; Level: SMD; POP?: NOPOP; Part Number: 63.R0034.1DL; Part Type: SMD-RG; SPEC: http://wpqssvr.wistron.com.tw:7001/wpqs/servlet/COM.qpart.Attachment?PartNumber=63.R0034.1DL; Status: NOPOP
R925 = 100R2F-L1-GP-U: CHIP RES 100 F 1/16W 0402; Category: BMC; GREENDFACTOR: R2_SA;R_SA;HF_SA;G_SA;; Level: SMD; POP?: NOPOP; Part Number: 64.10005.6DL; Part Type: SMD-RG; SPEC: http://wpqssvr.wistron.com.tw:7001/wpqs/servlet/COM.qpart.Attachment?PartNumber=64.10005.6DL; Status: NOPOP
R926 = 0R2J-2-GP: CHIP RES 0 J 1/16W 0402; Category: BMC; GREENDFACTOR: R2_SA;R_SA;HF_SA;G_SA;; Level: SMD; Part Number: 63.R0034.1DL; Part Type: SMD-RG; SPEC: http://wpqssvr.wistron.com.tw:7001/wpqs/servlet/COM.qpart.Attachment?PartNumber=63.R0034.1DL
R931 = 47KR2F-GP: CHIP RES 47K F 1/16W 0402; Category: BMC; GREENDFACTOR: R2_SA;R_SA;HF_SA;G_SA;; Level: SMD; POP?: NOPOP; Part Number: 64.47025.6DL; Part Type: RCL_GP; SPEC: http://wpqssvr.wistron.com.tw:7001/wpqs/servlet/COM.qpart.Attachment?PartNumber=64.47025.6DL
R936 = 4K7R2F-GP: CHIP RES 4.7K F 1/16W 0402; Category: BMC; GREENDFACTOR: R2_SA;HF_SA;G_SA;; Level: SMD; Part Number: 64.47015.6DL; Part Type: RCL_GP; SPEC: http://wpqssvr.wistron.com.tw:7001/wpqs/servlet/COM.qpart.Attachment?PartNumber=64.47015.6DL; Status: POP
R1036 = 10KR2F-2-GP: CHIP RES 10K F 1/16W 0402; GREENDFACTOR: R2_SA;HF_SA;G_SA;; POP?: NOPOP; Package Type: SMD-RG; Part Number: 64.10025.6DL; Part Type: SMD-RG; SPEC: http://wpqssvr.wistron.com.tw:7001/wpqs/servlet/COM.qpart.Attachment?PartNumber=64.10025.6DL
U166 = SN74LVC1G07DCKR-GP: IC CMOS 74LVC1G07DCKR SC70-5; GREENDFACTOR: R2_SA;; Part Number: 73.01G07.EHH; Part Type: DISCRET-G4; SPEC: http://wpqssvr.wistron.com.tw:7001/wpqs/servlet/COM.qpart.Attachment?PartNumber=73.01G07.EHH

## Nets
GND: BMC1.M1(ADC9_GPIX1) BMC1.M2(ADC8_GPIX0) BMC1.N1(ADC14_GPIX6) BMC1.N2(ADC13_GPIX5) BMC1.N3(ADC12_GPIX4) BMC1.N4(ADC11_GPIX3) BMC1.N5(ADC10_GPIX2) BMC1.P5(ADC15_GPIX7) BMC1.Y19(USB2AVSS) C76.2 C153.2 C154.2 C257.2 C258.2 C259.2 C260.2 C261.2 C262.2 C263.2 C264.2 C265.2 C266.2 C267.2 C268.2 C269.2 C495.2 C512.2 C7284.2 C7318.2 C7319.2 C7320.2 D2.3 D5.3 OSC2.2(GND) R180.1 R191.1 R200.1 R202.1 R205.1 R207.1 R208.1 R209.1 R211.1 R238.2 R354.2 R399.2 R400.2 R862.2 R872.1 R873.1 R909.2 R913.1 R917.1 R925.2 R926.2 R931.2 R2033.2 TC1.2 TC2.2 U30.3(GND) U32.3(GND) U82.2(GND) U166.3(GND) U169.1(GND) U169.9(GND) USB1.4(GND) USB1.7(GND_DRAIN) USB1.10 USB1.11 USB1.12 USB1.13 USB2.4(GND) USB2.7(GND_DRAIN) USB2.10(GND) USB2.11(GND) USB2.12(GND) USB2.13(GND) ; also on sheet 1 2 3 4 5 6 7 8 9 10 11 12 13 14 15 16 17 18 19 20 21 22 23 24 25 26 27 28 29 30 31 32 33 34 35 36 37 38 39 44 46 47 49 50 51 52 53 54 55 56 57 58 59 60 61 62 63 64 65 66 69 70 71 73 74 75 76 78 79 80 81 82 83 84 86 87 88 89 90 91 92 93 94 95 96 97 98 99 100 101 102 103 104 105 106 107 108 109 110 111 112 113 114 115 116 117 118 119 128 129 138 139 159 160 161 166 168 169 170 171 172 173 180 181 182 183 184
P1V05_PCH: C257.1 C258.1 C259.1 C260.1 C261.1 C263.1 C264.1 C265.1 ; also on sheet 10 45 87 173
P1V05_SUS_INT_CAP: C262.1 ; also on sheet 87
P3V3: Q21.G R213.1 R214.2 R218.1 R268.2 R348.2 R511.2 R515.2 R916.1 ; also on sheet 1 3 8 45 46 48 49 52 54 58 65 74 76 78 83 84 87 90 91 94 95 96 100 101 102 161 166 168 173 180 181 182 183
P3V3_STBY: C76.1 C154.1 L23.2 OSC2.4(VDD) R115.1 R116.1 R118.1 R119.1 R215.1 R333.1 R357.1 R358.2 R359.2 R367.2 R910.1 R911.1 R914.2 R915.1 R927.1 R930.1 R934.1 R936.1 R1036.1 R6609.1 R6610.1 U82.5(VCC) U166.5(VCC) ; also on sheet 2 3 5 6 8 9 10 11 12 15 16 17 20 21 22 25 26 27 30 31 33 34 35 37 38 39 45 47 49 50 51 52 54 55 59 60 61 62 63 64 65 66 69 70 71 72 73 74 76 79 83 84 87 88 89 90 91 92 93 94 95 96 97 98 99 159 161 166 168 173 180 182 183 184
P3V_BAT: R210.1 R212.1 ; also on sheet 84 87 173 184
P5V: C7318.1 U169.2(IN) ; also on sheet 45 59 66 69 76 80 82
P5V_USB_FRONT: C7320.1 R784.2 TC2.1 USB2.1(VBUS)
P5V_USB_FRONT_R: R784.1 U169.6(OUT2)
P5V_USB_INT: C7319.1 R851.2 TC1.1 USB1.1(VBUS)
P5V_USB_INT_R: R851.1 U169.7(OUT1)
PVCCIO: BMC1.V19(PECIVDD) R113.1 R114.1 R120.1 R121.1 R122.1 R123.1 R125.1 R126.1 R272.1 R273.1 ; also on sheet 11 16 26 35 39 46 47 68 87 97 100 101 102 103 120 129 130 139 160 173 182
VCCCLK3_3: C266.1 C267.1 C268.1 C269.1 ; also on sheet 87
ADC_12V_PCIE: BMC1.L5(ADC0_GPIW0) ; also on sheet 76
ADC_P1V05_STBY_PCH: BMC1.M3(ADC7_GPIW7) ; also on sheet 76
ADC_P1V8_STBY: BMC1.M4(ADC6_GPIW6) ; also on sheet 76
ADC_P3V3: BMC1.L3(ADC2_GPIW2) ; also on sheet 76
ADC_P3V3_STBY: BMC1.M5(ADC5_GPIW5) ; also on sheet 76
ADC_P3V3_VBAT: BMC1.L2(ADC3_GPIW3) ; also on sheet 184
ADC_P5V: BMC1.L4(ADC1_GPIW1) ; also on sheet 76
ADC_P5V_STBY: BMC1.L1(ADC4_GPIW4) ; also on sheet 76
ARM_NTRST: BMC1.E1(NTRST) C153.1 R910.2 R926.1
ARM_RTCK: BMC1.G4(RTCK) R913.2
ARM_TCK: BMC1.F2(TCK) R930.2 ; also on sheet 50
ARM_TDI: BMC1.F1(TDI_BDM) R911.2 ; also on sheet 50
ARM_TDO: BMC1.G3(TDO) R927.2 ; also on sheet 50
ARM_TMS: BMC1.G2(TMS) R915.2 ; also on sheet 50
AS_EXTRST_N: BMC1.E18(GPIOB7_EXTRST#_SPICS1#) R914.1 R925.1 R929.1
AUD_AZA_SDO: JP13.1 ; also on sheet 90
AUD_AZA_SDO_R: JP13.2 R215.2
BIOS_ERR_TRIGGER_N: BMC1.AA3(GPION6_PWM6_VPIG6) ; also on sheet 65 166
BMC_CURRENT_EN: BMC1.C21(GPIOY0_SIOS3#) ; also on sheet 52
BMC_RESET_N: BMC1.W20(SRST#) R924.2 R929.2 R931.1 R934.2 R2073.1 ; also on sheet 51 74
BOARD_ID0: BMC1.Y6(GPIOP0_TACH8_VPIR6) ; also on sheet 71
BOARD_ID1: BMC1.AB5(GPIOP1_TACH9_VPIR7) ; also on sheet 71
BOARD_ID2: BMC1.W7(GPIOP2_TACH10_VPIR8) ; also on sheet 71
BOARD_ID3: BMC1.AA6(GPIOP3_TACH11_VPIR9) ; also on sheet 71
BTN_FUNC_EN_N: BMC1.F20(GPIOY1_SIOS5#) ; also on sheet 168
CLK_33K_SUSCLK_PLD: R191.2 ; also on sheet 50 90
CPLD1_OK_HB: BMC1.AA2(GPION2_PWM2_VPIG2) R359.1 ; also on sheet 51
CPLD2_OK_HB: BMC1.AB2(GPION7_PWM7_VPIG7) R367.1 ; also on sheet 52
DB_PRESENT_BMC_N: BMC1.D13(GPIOG2_SGPSI0) ; also on sheet 69
ENTEST1: BMC1.E4(ENTEST) R917.2
FAN0_PWM_BMC: BMC1.W4(GPION0_PWM0_VPIG0) ; also on sheet 52 66
FAN0_TACH0A_BMC: BMC1.Y5(GPIOO1_TACH1_VPIG9) R348.1 ; also on sheet 66
FAN0_TACH_BMC: BMC1.V6(GPIOO0_TACH0_VPIG8) R268.1 ; also on sheet 66
FAN1_PWM_BMC: BMC1.Y3(GPION1_PWM1_VPIG1) ; also on sheet 52 66
FAN1_TACH1A_BMC: BMC1.AB3(GPIOO3_TACH3_VPIR1) R515.1 ; also on sheet 66
FAN1_TACH_BMC: BMC1.AA4(GPIOO2_TACH2_VPIR0) R511.1 ; also on sheet 66
FM_ADR_BMC_TRIGGER: BMC1.B5(GPIOA1_MAC2LINK) ; also on sheet 52
FM_ADR_COMPLETE: R787.1 ; also on sheet 51 166
FM_ADR_TRIGGER_EN: BMC1.A4(GPIOA2_TIMER3) ; also on sheet 52
FM_BMC_ADR_COMPLETE: BMC1.Y21(GPIOG5_WDTRST2_USBCKI) R787.2
FM_CPU0_BDX_PRSNT_LVT3_N: R116.2 ; also on sheet 11 51 139
FM_CPU0_SKTOCC_LVT3_N: R115.2 ; also on sheet 46 51 139
FM_CPU1_BDX_PRSNT_LVT3_N: R119.2 ; also on sheet 51 129
FM_CPU1_SKTOCC_LVT3_N: R118.2 ; also on sheet 46 51 129
FM_CPU_BMC_ERR0_CO_N: BMC1.U18(GPIOG7_FLWP#) Q21.D R357.2
FM_CPU_ERR0_CO_N: Q21.S ; also on sheet 102 166
FM_CPU_ERR1_CO_N: BMC1.K20(GPIOY3_SIOONCTRL#) ; also on sheet 51 102
FM_CPU_MSMI_LVT3_BMC_N: BMC1.A14(GPIOG0_SGPSCK) ; also on sheet 52 101
FM_PCH_LAN1_DISABLE_N: R872.2 ; also on sheet 64 90
FM_USB3_P0_EN_N: R399.1 U169.3(EN1) ; also on sheet 91
FM_USB3_P1_EN_N: R400.1 U169.4(EN2) ; also on sheet 91
H_CPU0_FAST_WAKE_G_N: R113.2 R117.1 ; also on sheet 139
H_CPU0_FIVR_FAULT_G: R123.2 ; also on sheet 101 138
H_CPU0_MSMI_G_N: R120.2 R252.1 ; also on sheet 139
H_CPU0_THERMTRIP_G_N: R122.2 ; also on sheet 101 139
H_CPU1_FAST_WAKE_G_N: R114.2 R117.2 ; also on sheet 129
H_CPU1_FIVR_FAULT_G: R126.2 ; also on sheet 101 128
H_CPU1_MSMI_G_N: R121.2 R259.2 ; also on sheet 129
H_CPU1_THERMTRIP_G_N: R125.2 ; also on sheet 101 129
H_CPU_MSMI_G_N: R252.2 R259.1 ; also on sheet 101
H_LVT3_CPU0_PROCHOT_OD_N: R916.2 ; also on sheet 98 180
H_LVT3_CPU1_PROCHOT_OD_N: R213.2 ; also on sheet 98 180
IRQ_BMC_PCH_NMI_NOA1_CLK: U82.1(B1) ; also on sheet 182
IRQ_BMC_PCH_NMI_NOA1_CLK_MUX: U82.4(A) ; also on sheet 90
IRQ_IBMC_PCH_SMI_LPC_N: BMC1.H19(GPIOB5_LPCPD#_LPCSMI#) ; also on sheet 90
IRQ_PVCCIN_CPU0_VRHOT_LVT3_N: BMC1.AB4(GPIOO6_TACH6_VPIR4) ; also on sheet 39 181
IRQ_PVCCIN_CPU1_VRHOT_LVT3_N: BMC1.V7(GPIOO7_TACH7_VPIR5) ; also on sheet 35 181
IRQ_PVDDQ_AB_VRHOT_LVT3_N: BMC1.AB1(GPION3_PWM3_VPIG3) ; also on sheet 31 181
IRQ_PVDDQ_CD_VRHOT_LVT3_N: BMC1.W5(GPION4_PWM4_VPIG4) ; also on sheet 26 181
IRQ_PVDDQ_EF_VRHOT_LVT3_N: BMC1.W6(GPIOO4_TACH4_VPIR2) ; also on sheet 21 181
IRQ_PVDDQ_GH_VRHOT_LVT3_N: BMC1.AA5(GPIOO5_TACH5_VPIR3) ; also on sheet 16 181
LPCRST_1: BMC1.E19(GPIOB4_LPCRST#) R751.1
MB0_CM_FAULT_N_R: BMC1.J3(GPIOJ3_SGPMI) ; also on sheet 60
MB_SLOT_ID0: BMC1.J5(GPIOJ0_SGPMCK) ; also on sheet 93
MB_SLOT_ID1: BMC1.J4(GPIOJ1_SGPMLD) ; also on sheet 93
MB_SLOT_ID2: BMC1.K5(GPIOJ2_SGPMO) ; also on sheet 93
NOA_8_GP21_PD: R200.2 ; also on sheet 91
NOA_10_FM_BIOS_ADV_FUNCTIONS: R214.1 R238.1 ; also on sheet 91
NVDIMM_PRSNT: BMC1.D6(GPIOA0_MAC1LINK) R771.2
NVDIMM_PRSNT_R: R771.1 ; also on sheet 51
OSC2_AS_CLKIN: BMC1.AB22(CLKIN) R923.2
OSC2_CONT: OSC2.1(OE) R936.2
OSC2_OUT: OSC2.3(OUTPUT) R923.1
PD_INTEGRATED_CLK_DIS: R873.2 U82.3(B0)
PD_PCH_GP51_GSXDOUT: R208.2 ; also on sheet 166
PD_PGDMON: R180.2 ; also on sheet 89
PD_USB2VRES: BMC1.AA20(USB2VRES) R909.1
PECI_BMC: BMC1.AA21(PECI) C7284.1 R2033.1 ; also on sheet 68
POWER_FAIL_BMC: BMC1.Y4(GPION5_PWM5_VPIG5) R752.1
POWER_FAIL_N: R752.2 ; also on sheet 48 52 54 61 93
PS_REDUNDANT_LOST_N: BMC1.E6(GPIOA3_TIMER4) R358.1 ; also on sheet 93
PU_CPU0_EAR_G_N: R273.2 ; also on sheet 139
PU_CPU1_EAR_G_N: R272.2 ; also on sheet 129
PU_PCH_DSWODVREN: R210.2 R211.2 ; also on sheet 90
PU_PCH_INTVRMEN: R212.2 ; also on sheet 90
PWRGD_P1V05_PCH_STBY_DLY: R205.2 ; also on sheet 51 90
PWRGD_PCH_PWROK: R207.2 ; also on sheet 51 52 90
PWRGD_SYS_PWROK: R202.2 ; also on sheet 51 52 90
REVISION_ID0: BMC1.AB6(GPIOP4_TACH12) ; also on sheet 71
REVISION_ID1: BMC1.Y7(GPIOP5_TACH13) ; also on sheet 71
REVISION_ID2: BMC1.AA7(GPIOP6_TACH14_BMCINT) ; also on sheet 71
REVISION_ID3: BMC1.AB7(GPIOP7_TACH15_FLACK) ; also on sheet 71
RST_PCIE_PCH_N: R209.2 ; also on sheet 48 51
RST_PLTRST_BUF_N: R751.2 ; also on sheet 51 52 78
RST_PLTRST_N: BMC1.AA22(GPIOG6_FLBUSY#) U82.6(S) ; also on sheet 51 90 100
RST_RSMRST_N: U166.2(A) ; also on sheet 51 52 182
SMB_1_ME_PCH_SDA: R330.2 ; also on sheet 161
SMB_1_ME_PCH_SDA_LT_STRAP: R330.1 R862.1 ; also on sheet 166
SPEAKER_PCH: R218.2 ; also on sheet 65 90
U166_Y: R1036.2 R2073.2 U166.4(Y)
USB2_00_DN: R757.2 ; also on sheet 92
USB2_00_DP: R756.2 ; also on sheet 92
USB2_01_DN: L7.1 ; also on sheet 92
USB2_01_DN_FB: D2.1 L7.2 USB1.2(D-)
USB2_01_DP: L7.4 ; also on sheet 92
USB2_01_DP_FB: D2.2 L7.3 USB1.3(D+)
USB2_02_DN: L38.1 ; also on sheet 92
USB2_02_DP: L38.4 ; also on sheet 92
USB2_02_INT_CN_DN: D5.2 L38.2 USB2.2(D-)
USB2_02_INT_CN_DP: D5.1 L38.3 USB2.3(D+)
USB2_DN: BMC1.AB20(USB2_DN/USB2_HDN) R757.1
USB2_DP: BMC1.AB21(USB2_DP/USB2_HDP) R756.1
USB2_OC0_INT_N: R6610.2 U169.8(FLG1) ; also on sheet 48
USB2_OC1_FP_N: R6609.2 U169.5(FLG2) ; also on sheet 48
USB3_01_RXN: L28.4 R594.1 ; also on sheet 92
USB3_01_RXN_FB: L28.3 R594.2 U32.5(I/O#5) U32.6(NC#6) USB1.5(STDA_SSR-)
USB3_01_RXP: L28.1 R598.1 ; also on sheet 92
USB3_01_RXP_FB: L28.2 R598.2 U32.4(I/O#4) U32.7(NC#7) USB1.6(STDA_SSR+)
USB3_01_TXN: C335.1 ; also on sheet 92
USB3_01_TXN_C: C335.2 L35.4 R578.1
USB3_01_TXN_FB: L35.3 R578.2 U32.2(I/O#2) U32.9(NC#9) USB1.8(STDA_SST-)
USB3_01_TXP: C334.1 ; also on sheet 92
USB3_01_TXP_C: C334.2 L35.1 R326.1
USB3_01_TXP_FB: L35.2 R326.2 U32.1(I/O#1) U32.10(NC#10) USB1.9(STDA_SST+)
USB3_02_RXN: L47.1 R599.1 ; also on sheet 92
USB3_02_RXN_FB: L47.2 R599.2 U30.1(I/O#1) U30.10(NC#10) USB2.5(SSRX-)
USB3_02_RXP: L47.4 R331.1 ; also on sheet 92
USB3_02_RXP_FB: L47.3 R331.2 U30.2(I/O#2) U30.9(NC#9) USB2.6(SSRX+)
USB3_02_TXN: C332.1 ; also on sheet 92
USB3_02_TXN_C: C332.2 L31.1 R595.1
USB3_02_TXN_FB: L31.2 R595.2 U30.4(I/O#4) U30.7(NC#7) USB2.8(SSTX-)
USB3_02_TXP: C333.1 ; also on sheet 92
USB3_02_TXP_C: C333.2 L31.4 R577.1
USB3_02_TXP_FB: L31.3 R577.2 U30.5(I/O#5) U30.6(NC#6) USB2.9(SSTX+)
USBV33A: BMC1.W18(USB2AV33) C495.1 C512.1 L23.1
UV_FPH_EN: BMC1.E13(GPIOG1_SGPSLD) ; also on sheet 52
UV_FPH_LEVEL_SEL: BMC1.C13(GPIOG3_SGPSI1) R333.2 R354.1 ; also on sheet 61
VOLTAGE_ALERT_N: BMC1.G20(GPIOY2_SIOPWREQ#) ; also on sheet 52 61
WDTRST: BMC1.B13(GPIOG4_WDTRST1_OSCCLK) R924.1

Not connected (* = marked no-connect by the designer): BMC1 H20(GPIOB6_LPCPME#)* J1(USB11_HDP)* J2(USB11_HDN)* K3(USB11_DN/USB11_HDN2)* K4(USB11_DP/USB11_HDP2)* R2(DACR)* R3(DACG)* R4(DACB)* T1(DDCDAT_GPIOJ7)* T2(DDCCLK_GPIOJ6)* T4(VGAHS_GPIOJ4)* U2(VGAVS_GPIOJ5)*; U30 8(NC#8)*; U32 8(NC#8)*; U166 1(NC#1)*

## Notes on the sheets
sheet 174
- WELLSBURG - STRAPPING/MISC
- TO WBG
- DESIGN NOTE:
  RING  OSCILLATOR   BYPASS.
  P/U:  RING  OSCILLATOR   BYPASS  IS  DISABLED   (DEFAULT).
  P/D:  RING  OSCILLATOR   BYPASS  IS  ENABLED.
  PCH  PROVIDES   WEAK  INTERNAL   P/U  (15K-40K).
- CAD NOTE: PLACE RES AS CLOSE AS POSSIBLE TO WBG
- DESIGN NOTE:
  PLL ON-DIE VOLTAGE REGULATOR ENABLE
  ENABLED WHEN SAMPLED HIGH
  DISABLED WHEN SAMPLED LOW
  WEAK INTERNAL PULL-UP (15K - 40K)
- PCH PROVIDES WEAK INTERNAL P/U (15K-40K).
- DESIGN NOTE:
  NO REBOOT
  REBOOT DISABLE WHEN HIGH
  INTERNAL PULL DOWN (15K-40K)
- DESIGN NOTE:
  INTEGRATED CLOCK CHIP DISABLE.
  ENABLED WHEN SAMPLED LOW.
  INTERNAL PULL-UP (15K-40K).
- INTERATED CLOCK CHIP ENABLED FOR PPO AND PO.
- DESIGN NOTE:
  DFXTESTMODE ACTIVE
  DFXTESTMODE ACTIVE
  P/D: TEST MODE IS ENABLED
  PCH PROVIDES WEAK INTERNAL P/U (8K-15K)
- DESIGN NOTE:
  TLS  CONFIDENTIALITY   ENABLE.
  ENABLED   WHEN  SAMPLED   HIGH  (DEFAULT).
  DISABLED   WHEN  SAMPLED   LOW.
  INTERNAL   PD  (15K-40K).
- DESIGN NOTE:
  DSWODVREN: DEEP SLEEP WELL ON-DIE VOLTAGE REGULATOR ENABLE-
  P/U: DSW ODVR IS ENABLED (DEFAULT)
  P/D: DSW ODVR IS DISABLED
- BOOT BIOS STRAPS (BBS)
- GNT[1]_GSXDOUT
  BBS[1]
- BIOS_SPI_WP
  BBS[0]
- 0
- 0
- LPC
- 1
- 1
- SPI <DEFAULT>
- INTERNAL PULL-UP (15K-40K).
  DISABLED AFTER PLTRST# DEASSERTS.
- FAB1 REV005 20150322
- DESIGN NOTE:
  INTERNAL VRM ENABLE: THIS SIGNAL IS USED TO ENABLE OR DISABLE THE INTEGRATED 1.05
  VOLTAGE REGULATORS FOR THE SUSPEND WELL ON THE WELLSBURG
  P/U: ENABLED VR (DEFAULT)
  P/D: DISABLES VR
  P/D OPTION NOT BEING PROVIDED
- DESIGN NOTE:
  LT KEY DOWNGRADE.
  POP R330: LT DEBUG MODE IS DISABLED WHEN PULLED HIGH (DEFAULT).
  POP R862: LT DEBUG MODE IS ENABLED WHEN PULLED LOW.
- THIS PIN IS SHARED WITH MEXP_BMBDATA1. IF THIS FEATURE NEEDS TO BE ENABLED.
  PLEASE SET THE JUMPER TO 2-3 BEFORE PLTRST# AND THEN RETURN TO 1-2 FOR SMBUS FUNCTIONALITY.
- DESIGN NOTE:
  WBG DMI RX TERMINATION
  IN AC-COUPLED MODE:
  0: DMI RX IS TERMINATED TO VSS.
  1: DMI RX IS TERMINATED TO COMMON MODE.
- FAB1 20150217
- FLASH DESCRIPTOR SECURITY OVERRIDE.
  * FLASH DESCRIPTOR SECURITY OVERRIDE WHEN HIGH
    SET JUMPER.
  * FLASH DESCRIPTOR SECURITY NO OVERRIDE WHEN LOW
    (DEFAULT, NO JUMPER).
  INTERNAL PD (9K-50K). MANUFACTURING JUMPER ALSO
  CAN BE USED TO SET THIS STRAP.
sheet 175
- WELLSBURG - DECOUPLING (2/2)
- P1V05_PCH PCH DECOUPLING
- GPIO/LPC $SECTION
- NOT USED IN DESKTOP TP IS OK
- 1.05V CORE CLOCK INTEGRATION
- CAD NOTE:
  PLACE CAP
  BSC STYLE
  NEAR TO PIN
  VCCSSCF100_1P05
- CAD NOTE:
  PLACE CAP
  NEAR TO PIN
  VCCSUS_1P05
- VCCCLKF100_1P05
- VCCSSCFF_1P05
- VCCSSCF135_1P05
- VCCCLKF100OC_1P05
- VCCCLKF135_1P05
- SUSPEND POWER FOR USB: 1.0 V / 1.1 V FOR USB.
  THIS POWER IS SUPPLIED BY THE SUSPEND WELL.
  IN INTERNAL VR MODE, THIS IS SUPPLIED
  INTERNALLY.  A CAPACITOR MAY BE
  REQUIRED ON THE BOARD
- CAD NOTE: BOARD (R) STYLE PLACE CAPACITOR NEAR TO PIN
- ROOM=WBG_DECOUPLING
- 1.05V SATA3X $SECTION
- P3V3 PCH DECOUPLING
- 3.3V CORE CLOCK INTEGRATION
- CAD NOTE:
  BSC STYLE
  PLACE 2 CAPS
  NEAR TO PINS
  VCCSATAXA_1P05
- CAD NOTE:
  PLACE CAP
  (R) STYLE
  NEAR TO PIN
  VCCSATAXA_1P05
- VCCASEFLEX23_3P3
- VCCASEFLEX0_3P3
- VCCASEPCI_3P3
- VCCASEFLEX1_3P3
- CAD NOTE: BOARD (R) STYLE PLACE CAPACITOR NEAR TO PIN
sheet 176
- Vertical  USB
- Front  USB
- 3/4 POP IN SA
- 3/4 POP IN SA
- 3/4 POP IN SA
- 3/4 POP IN SA
- FAB1 20150212
- FAB1 20150212
- FAB2 REV001 20150701
- FAB2 REV001 20150610
- FAB1 20150126
sheet 177
- AST1250 CLK / VGA / USB / JTAG
- AST1250 not support VGA
- FAB1 20150312
- FAB1 REV007 20150325
- FAB1 REV004 20150320
- FAB1 20150126
- FAB1 REV010 20150331
- FAB1 REV004 20150320
- FAB1 REV012 20150409
- FAB1 REV002 20150317
- These 4 pins N1~N3,P5 pin
  can NC in AST1250.
- FAB1 20150306
- FAB1 REV005 20150323
- FAB1 REV005 20150323
- FAB1 REV005 20150323
- FAB1 REV014 20150416
- FAB1 20150210
- Change to 84.27002.N31
- JTAG
- FAB1 20150126
- Pull low NTRST pin to disable the JTAG Slave function.
- Layout Note:
  Place JTAG TP
  on bottom side.
- FAB1 REV014 20150416
sheet 178
- POWER GOOD/RESET DIAGRAM
- STBY power
- P12V_MAIN
- P12V_STBY
- U2
- PU52
- 1
- 2
- PWRGD_P5V_STBY
- 3
- ADM1278
- P5V_STBY
- Normal power
- P.129
- P.175
- PU44
- PWRGD_P5V_STBY
- U35
- P3V3_STBY
- PWRGD_P3V3_AUX
- 4
- CKMNG
- RESET signal
- P.177
- P.130
- P.134
- U18
- PU41
- PU40
- PU42
- P12V_HDD_FAN1
- P1V8_STBY
- PWRGD_P1V8_STBY
- P1V538_STBY
- PWRGD_P1V538_STBY
- P1V26_STBY
- P.130
- P.172
- P.173
- P.174
- U47
- P.138
- 12
- FM_PS_EN
- PWRGD_PS_PWROK
- 13
- P3V3_STBY
- PT2D
- P12V_PCIE_HDD
- U22
- 5
- R731
- 5
- ADM809
- RST_RSMRST_R_N
- RST_RSMRST_N
- RST_RSMRST_N
- PB5A
- P12V_STBY
- 13
- PWRGD_PS_PWROK
- 0R
- TO BMC & CPLD
- PU39
- PL4B
- P.94
- 7
- P1V05_STBY_PCH
- PWRGD_P1V05_STBY_PCH_P1V0_STBY
- PB2A
- 14
- P5V
- 13
- PB3D
- PWRGD_P5V
- PWRGD_PS_PWROK
- Q24
- TO DPWROK & RSMRST#
- P.82 - 93
- P.130
- 5
- 6
- RST_RSMRST_PCH_N
- RSMRST#
- SLP_A#
- FM_SLPA_N
- 9
- Q1
- P.148
- FP_PWRBTN_N
- PWRBTN_FP_N
- PWRBTN_OUT_N
- FM_SLPS3_N
- TO BMC & CPLD
- 11
- 22
- PWRGD_PVPP_PVDDQ_AB
- PVDDQ_AB
- PVPP_AB_PWRGD
- PWRON1
- GATE
- PCH
- SLP_S3#
- PT3A
- PB4C
- PG
- EN
- TO BMC
- PWRGD_P1V05_PCH_STBY_DLY
- PL9B
- PU13
- P.153
- BTN_FUNC_EN_N
- R287
  0R
- 22
- PVDDQ_CD
- P.108 - 110
- 8
- PB4D
- PWRGD_PVPP_PVDDQ_CD
- PG
- EN
- PVPP_CD_PWRGD
- SYS_PWRBTN_N
- BMC_PWRBTN_N
- AND
  GATE
- FM_BMC_PWRBTN_OUT_N
- 10
- PWRGD_PCH_APWROK
- PU19
- PWRBTN#
- APWROK
- P.152
- BMC
- NOPOP
- R288
  0R
- 20
- PVPP_AB(2V5)
- 21
- 26
- PB4B
- FM_VPP_MEM_ABCD_EN
- PVPP_AB_PWRGD
- TO BMC
- PWRGD_PCH_PWROK
- EN
- PU18
- PG
- SYS_RSTBTN_N
- RSTBTN_BMC_OUT
- AND
  GATE
- RST_BMC_RSTBTN_OUT_N
- PCH_PWROK
- PL2B
- CPLD
- P.157
- U23
- 31
- PVPP_CD(2V5)
- PVPP_CD_PWRGD
- 21
- BUF
- SYS_PWROK
- PWRGD_SYS_PWROK
- PL5C
- EN
- PU24
- PG
- BTN_FUNC_EN_N
- RST_PCH_RSTBTN_N
- 32
- FP_RSTBTN_N
- RSTBTN_FP_N
- RSTBTN_OUT_N
- SYS_RESET#
- RST_PLTRST_N
- RESET1
- GATE
- PLTRST#
- PB3C
- P.158
- 28
- PR5A
- 22
- PWRGD_PVPP_PVDDQ_EF
- PVDDQ_EF
- PVPP_EF_PWRGD
- PG
- PU25
- EN
- PVCCIO
- PVCCIO
- PVDDQ_AB
- PROCPWRGD
- PWRGD_CPUPWRGD
- PL2A
- P.163
- 27
- 22
- PWRGD_PVPP_PVDDQ_GH
- PVDDQ_GH
- PVPP_GH_PWRGD
- R103
  49D9R
- R104
  49D9R
- R101
  64D9R
- DRAMPWROK
- PWRGD_DRAMPWRGD_CO
- PR6A
- PG
- PU31
- EN
- 30
- 29
- P.162
- PWRGD_CPU0_G
- PWRGD_CPU0_LVC3
- PT2C
- 20
- FM_VPP_MEM_EFGH_EN
- PVPP_EF(2V5)
- PVPP_EF_PWRGD
- 21
- XDP
- CPU0
- PR7A
- EN
- PG
- RST_CPU0_G_N
- 34
- GTL2014PW
- RST_CPU0_LVC3_N
- 33
- PU30
- PL5A
- P.167
- 28
- U16
- 27
- PVPP_GH(2V5)
- 21
- PWRGD_CPU0_AB_DRAM_G
- PWRGD_DRAMPWRGD_CO
- EN
- PG
- PVPP_GH_PWRGD
- PU36
- R1099
  300R
- FROM CPLD
- P.180
- P.25- 37
- PVCCIO
- PVCCIO
- PVDDQ_EF
- 17
- FM_P3V3_CPLD_EN
- P3V3
- PWRGD_P3V3
- 18
- PL5B
- EN
- PG
- PU51
- R109
  49D9R
- R110
  49D9R
- R107
  64D9R
- P.176
- PWRGD_CPU1_G
- 30
- PWRGD_CPU1_LVC3
- 29
- 18
- PWRGD_P3V3
- PL4A
- PT4F
- CPU1
- RST_CPU1_G_N
- 34
- GTL2014PW
- RST_CPU1_LVC3_N
- 33
- PL3D
- P1V5_PCH
- PL8B
- 19
- PWRGD_P1V5_PCH
- PWRGD_P3V3
- 18
- 28
- U17
- 27
- PG
- PU43
- EN
- PWRGD_CPU1_EF_DRAM_G
- PWRGD_DRAMPWRGD_CO
- P.171
- R1103
  300R
- FROM CPLD
- P.38 - 61
- 15
- PVCCIO
- PT4B
- FM_VCC_MAIN_EN
- PWRGD_P1V5_PCH
- P3V3
- EN
- PU37
- PG
- P.168
- R456
  4K7R
- P1V05_PCH
- PWRGD_P1V05_PCH
- DB1
- EN
- PU38
- PG
- DB1900Z -
  CLOCK BUFFER
- R653
- 25
- 16
- P.169
- PWRGD_DB1900Z
- FM_PLD_CLK_EN
- PT2E
- PL3C
- PWRGD_P1V05_PCH
- 0R
- P.131
- PVCCIN_CPU0
- 23
- PWRGD_PVCCIN_CPU0
- PG
- EN
- PVCCIN_CPU0_EN
- PL3A
- PU1
- P.140
- PVCCIN_CPU1
- 23
- 33
- PWRGD_PVCCIN_CPU1
- PVCCIN_CPU1_EN
- PL7A
- PR7D
- RST_PCIE_PCH_DEV_N
- PG
- PU7
- EN
- MEZCN1
- NGFF1
- P.79
- P.96
- P.144
- 33
- RST_PERST0_N
- PWRGD_PVCCIN_CPU0
- 24
- PR2A
- PR7C
- MEZZ CONN
- NGFF CONN
- PWRGD_PVCCIN_CPU1
- 24
- PCIE1
- BMC1A
- PT4E
- P.80
- P.108 - 110
- BMC
- PCIE RISER
- PCI-Express
- MIDCN2
- P.81
- LAN1
- P.125- 127
- MID-PLANE
  CONN
- INTEL I210
sheet 179
- CPU SIDE BAND - PULL UP/DN
- Place close to CPU0
  within 1"
- Place close to CPU1
  within 1"
- CAD NOTE:
  PACKAGE PINS PULL-UPS. PLACE NEAR TO CPU.
- TO/FROM
  CPU1
- TO/FROM
  CPU2
- FAB1 REV005 20150323
- CAD NOTE:
  PLACE NEAR GTL2014
- When Enhanced Machine Check Architecture Generation 2 (EMCA2) is disabled, the
  MSMI_N pin is not used. When EMCA2 is enabled, the CATERR_N signal will no longer
  be driven and instead the processor will drive the MSMI_N signal. Platforms that
  enable EMCA2, should monitor MSMI_N for uncorrectable and fatal events, and at a
  minimum, reset the system on fatal events as is the case for CATERR_N.
- CAD NOTE:
  PLACE NEAR TO RESPECTIVE CPU.
- FAB1 20150305
